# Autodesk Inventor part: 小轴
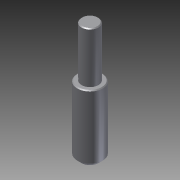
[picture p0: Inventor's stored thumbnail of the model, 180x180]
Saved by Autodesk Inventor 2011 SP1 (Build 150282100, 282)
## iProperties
Created: 2013-12
Part Number: 小轴
Document SubType Name: Modeling
Designer: Administrator
Density: 1 g/cm^3
Author: Administrator
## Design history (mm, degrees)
sketch "草图1"
  geometry: C1 r 3 at (0, 0); 1 further point
  constraints: 1 centre point, 1 coincident
  dimensions: "d0" = 6 diameter of C1
extrude "拉伸1" new body sketch "草图1" distance "d1" = 16; taper "d2" = 0 deg
sketch "草图2"
  geometry: C1 r 3 at (0, 0) reference; C2 r 2 at (0, 0)
  constraints: 1 centre point, 1 coincident
  dimensions: "d3" = 4 diameter of C2
extrude "拉伸2" join sketch "草图2" distance "d4" = 12; taper "d5" = 0 deg
chamfer "倒角1" distance "d6" = 1; stored, may be unused: second distance "d7" = 2, angle "d8" = 45 deg
chamfer "倒角2" distance "d9" = 0.2; stored, may be unused: second distance "d10" = 2, angle "d11" = 45 deg
node "实体1"
